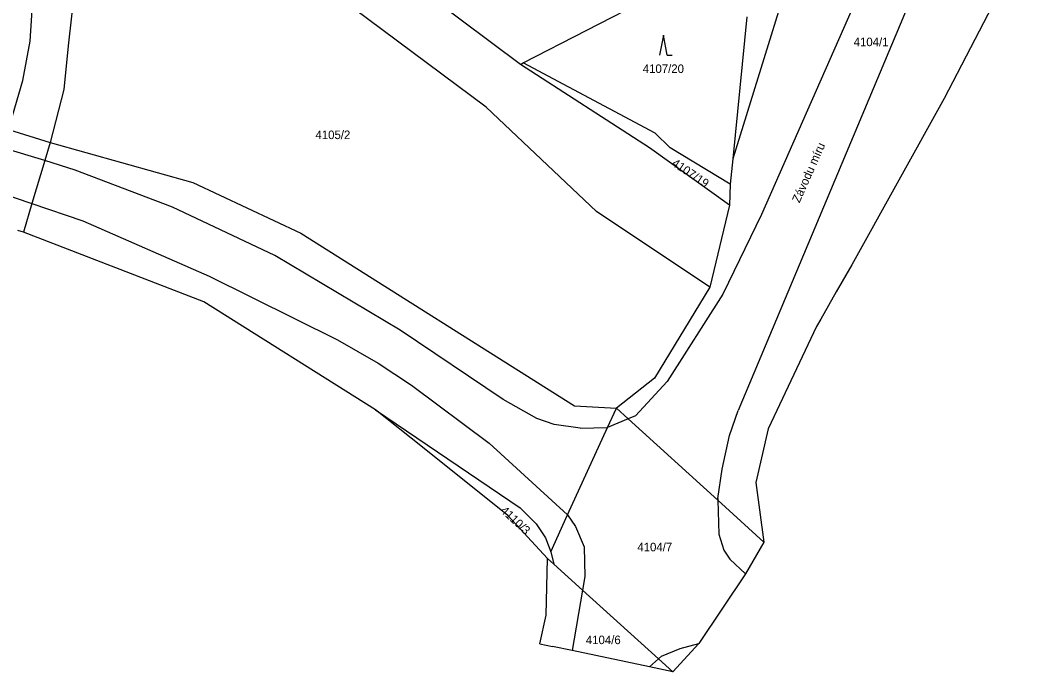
# Model space of a CAD drawing. Extents: x -869103 to -863415, y -1015889 to -1012477.
# Drawn here: x -865887.9 to -865688.1, y -1015653.3 to -1015523.3 of the extents above; entities that cross this region are included whole.
import ezdxf

# ---------------------------------------------------------------- set-up
doc = ezdxf.new("R2010")
doc.units = 0
for name, color, linetype in [('Hranice katastralního území', 7, 'Continuous'), ('Hranice parcel', 7, 'Continuous'), ('Parcelní čísla', 7, 'Continuous'), ('Pop  PČ popisy', 7, 'Continuous'), ('Vnitřní kresba', 7, 'Continuous'), ('Značky kultur', 7, 'Continuous')]:
    doc.layers.add(name, color=color, linetype=linetype)

msp = doc.modelspace()

# ---------------------------------------------------------------- linework, layer by layer
at = {"layer": 'Hranice katastralního území'}
for p, q in [((-865887.26, -1015565.58), (-865888.39, -1015565.31)), ((-865784.36, -1015647.63), (-865781.8, -1015648.17)), ((-865752.64, -1015647.56), (-865757.86, -1015653.26))]:
    msp.add_line(p, q, dxfattribs=at)
for points in [[(-865688.07, -1015508.76), (-865703.74, -1015538.94), (-865722.18, -1015572.15)], [(-865817.08, -1015601), (-865851.33, -1015579.49), (-865887.26, -1015565.58)], [(-865722.18, -1015572.15), (-865725.26, -1015577.53), (-865728.36, -1015582.94), (-865729.2, -1015584.4)], [(-865729.2, -1015584.4), (-865738.82, -1015604.83), (-865741.3, -1015615.52), (-865739.69, -1015627.38)], [(-865782.8, -1015630.68), (-865790.73, -1015622.05), (-865807.7, -1015608.48), (-865817.08, -1015601)], [(-865739.69, -1015627.38), (-865743.36, -1015633.68), (-865752.64, -1015647.56)], [(-865784.36, -1015647.63), (-865783.09, -1015641.97), (-865782.8, -1015630.68)], [(-865757.86, -1015653.26), (-865762.52, -1015652.27), (-865777.93, -1015649), (-865781.8, -1015648.17)]]:
    msp.add_lwpolyline(points, dxfattribs=at)
at = {"layer": 'Hranice parcel'}
for p, q in [((-865787.68, -1015531.83), (-865753.86, -1015514.46)), ((-865788.19, -1015532.18), (-865807.64, -1015517.64)), ((-865743.07, -1015522.7), (-865745.89, -1015551.01)), ((-865788.19, -1015532.18), (-865787.68, -1015531.83)), ((-865890.21, -1015545.13), (-865887.36, -1015535.4)), ((-865879.2, -1015537.17), (-865881.95, -1015547.71)), ((-865890.21, -1015545.13), (-865881.95, -1015547.71)), ((-865745.89, -1015551.01), (-865746.43, -1015556.04)), ((-865746.43, -1015556.04), (-865746.55, -1015560.23)), ((-865746.55, -1015560.23), (-865750.44, -1015576.59)), ((-865887.26, -1015565.58), (-865888.39, -1015565.31)), ((-865782.17, -1015629.29), (-865781.59, -1015631.77)), ((-865781.59, -1015631.77), (-865782.8, -1015630.68)), ((-865784.36, -1015647.63), (-865781.8, -1015648.17)), ((-865752.64, -1015647.56), (-865757.86, -1015653.26))]:
    msp.add_line(p, q, dxfattribs=at)
for points in [[(-865717.62, -1015450.27), (-865729.73, -1015498.87), (-865745.89, -1015551.01)], [(-865750.44, -1015576.59), (-865773.08, -1015561.48), (-865795.05, -1015540.71), (-865842.08, -1015505.65), (-865869.48, -1015480.31), (-865882.71, -1015470.11)], [(-865887.36, -1015535.4), (-865885.92, -1015527.56), (-865885.14, -1015515.21), (-865885.23, -1015501.36), (-865887.15, -1015481.68)], [(-865881.27, -1015481.01), (-865878.01, -1015500.53), (-865876.93, -1015515.95), (-865878.33, -1015528.44), (-865879.2, -1015537.17)], [(-865688.07, -1015508.76), (-865703.74, -1015538.94), (-865722.18, -1015572.15)], [(-865746.43, -1015556.04), (-865758.39, -1015548.79), (-865761.34, -1015545.87), (-865787.68, -1015531.83)], [(-865746.55, -1015560.23), (-865762.5, -1015548.79), (-865788.19, -1015532.18)], [(-865881.95, -1015547.71), (-865853.5, -1015555.73), (-865831.95, -1015565.83), (-865777.46, -1015600.23), (-865769.1, -1015600.7)], [(-865817.08, -1015601), (-865851.33, -1015579.49), (-865887.26, -1015565.58)], [(-865722.18, -1015572.15), (-865725.26, -1015577.53), (-865728.36, -1015582.94), (-865729.2, -1015584.4)], [(-865750.44, -1015576.59), (-865761.52, -1015594.71), (-865769.1, -1015600.7)], [(-865729.2, -1015584.4), (-865738.82, -1015604.83), (-865741.3, -1015615.52), (-865739.69, -1015627.38)], [(-865782.8, -1015630.68), (-865790.73, -1015622.05), (-865807.7, -1015608.48), (-865817.08, -1015601)], [(-865817.08, -1015601), (-865788.25, -1015620.52), (-865785.07, -1015623.77), (-865783.22, -1015626.51), (-865782.17, -1015629.29)], [(-865782.17, -1015629.29), (-865778.82, -1015621.97), (-865770.87, -1015604.57), (-865769.1, -1015600.7)], [(-865769.1, -1015600.7), (-865766.76, -1015602.82), (-865748.87, -1015619.05), (-865739.69, -1015627.38)], [(-865739.69, -1015627.38), (-865743.36, -1015633.68), (-865752.64, -1015647.56)], [(-865784.36, -1015647.63), (-865783.09, -1015641.97), (-865782.8, -1015630.68)], [(-865757.86, -1015653.26), (-865760.73, -1015650.66), (-865775.84, -1015636.98), (-865781.59, -1015631.77)], [(-865757.86, -1015653.26), (-865762.52, -1015652.27), (-865777.93, -1015649), (-865781.8, -1015648.17)]]:
    msp.add_lwpolyline(points, dxfattribs=at)
at = {"layer": 'Vnitřní kresba'}
for p, q in [((-865716.89, -1015509.26), (-865740.14, -1015562.12)), ((-865707.02, -1015511.02), (-865744.84, -1015601.17)), ((-865881.95, -1015547.71), (-865883.03, -1015551.35)), ((-865883.03, -1015551.35), (-865891.15, -1015548.86)), ((-865883.03, -1015551.35), (-865885.57, -1015559.9)), ((-865876.92, -1015553.23), (-865883.03, -1015551.35)), ((-865857.57, -1015560.65), (-865876.92, -1015553.23)), ((-865893.28, -1015557.29), (-865885.57, -1015559.9)), ((-865885.57, -1015559.9), (-865887.26, -1015565.58)), ((-865885.57, -1015559.9), (-865875.43, -1015563.34)), ((-865837.19, -1015570.29), (-865857.57, -1015560.65)), ((-865875.43, -1015563.34), (-865850.25, -1015574.37)), ((-865740.14, -1015562.12), (-865747.9, -1015577.95)), ((-865812.16, -1015585.16), (-865837.19, -1015570.29)), ((-865850.25, -1015574.37), (-865824.65, -1015587.09)), ((-865747.9, -1015577.95), (-865758.94, -1015595.35)), ((-865791.67, -1015598.96), (-865812.16, -1015585.16)), ((-865824.65, -1015587.09), (-865816.57, -1015591.73)), ((-865816.57, -1015591.73), (-865809.91, -1015596.13)), ((-865758.94, -1015595.35), (-865765.3, -1015602.2)), ((-865809.91, -1015596.13), (-865794.43, -1015607.65)), ((-865784.94, -1015602.72), (-865791.67, -1015598.96)), ((-865746.55, -1015606.13), (-865744.84, -1015601.17)), ((-865781.49, -1015603.92), (-865784.94, -1015602.72)), ((-865776.33, -1015604.7), (-865781.49, -1015603.92)), ((-865766.76, -1015602.82), (-865770.87, -1015604.57)), ((-865765.3, -1015602.2), (-865766.76, -1015602.82)), ((-865776.33, -1015604.7), (-865770.87, -1015604.57)), ((-865794.43, -1015607.65), (-865778.82, -1015621.97)), ((-865748.03, -1015612.87), (-865746.55, -1015606.13)), ((-865748.88, -1015618.71), (-865748.03, -1015612.87)), ((-865748.88, -1015618.71), (-865748.87, -1015619.05)), ((-865748.87, -1015619.05), (-865748.67, -1015625.8)), ((-865778.82, -1015621.97), (-865777.24, -1015624.24)), ((-865777.24, -1015624.24), (-865775.54, -1015628.33)), ((-865748.67, -1015625.8), (-865747.66, -1015628.97)), ((-865775.54, -1015628.33), (-865775.36, -1015634.25)), ((-865747.66, -1015628.97), (-865746.5, -1015630.75)), ((-865746.5, -1015630.75), (-865743.36, -1015633.68)), ((-865775.36, -1015634.25), (-865775.84, -1015636.98)), ((-865775.84, -1015636.98), (-865777.93, -1015649)), ((-865756.35, -1015648.6), (-865752.64, -1015647.56)), ((-865760.1, -1015650.1), (-865756.35, -1015648.6)), ((-865762.52, -1015652.27), (-865760.73, -1015650.66)), ((-865760.73, -1015650.66), (-865760.1, -1015650.1))]:
    msp.add_line(p, q, dxfattribs=at)
at = {"layer": 'Značky kultur'}
for p, q in [((-865759.72, -1015526.33), (-865760.47, -1015530.33)), ((-865758.97, -1015530.33), (-865759.72, -1015526.33)), ((-865758.97, -1015530.33), (-865757.97, -1015530.33))]:
    msp.add_line(p, q, dxfattribs=at)

# ---------------------------------------------------------------- texts
at = {"layer": 'Parcelní čísla'}
for s, p in [('4104/1', (-865721.81, -1015528.54)), ('4107/20', (-865763.84, -1015533.88)), ('4105/2', (-865829.07, -1015547.06)), ('4104/7', (-865764.92, -1015629.22)), ('4104/6', (-865775.18, -1015647.72))]:
    msp.add_text(s, height=1.7, dxfattribs=at).set_placement(p)
for s, rotation, p in [('4107/19', 326, (-865758.19, -1015552.23)), ('4110/3', 317, (-865792.31, -1015621.28))]:
    msp.add_text(s, height=1.7, rotation=rotation, dxfattribs=at).set_placement(p)
at = {"layer": 'Pop  PČ popisy'}
msp.add_text('Závodu míru', height=1.7, rotation=66, dxfattribs=at).set_placement((-865732.61, -1015559.89))

doc.saveas('drawing.dxf')
